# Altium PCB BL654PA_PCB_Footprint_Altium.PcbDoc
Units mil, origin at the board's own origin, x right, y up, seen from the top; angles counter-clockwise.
Board outline 866.14 x 393.7 mil, 2 copper layers (Top Layer, Bottom Layer); 1 components, 0 nets, 80 pads, 0 vias.
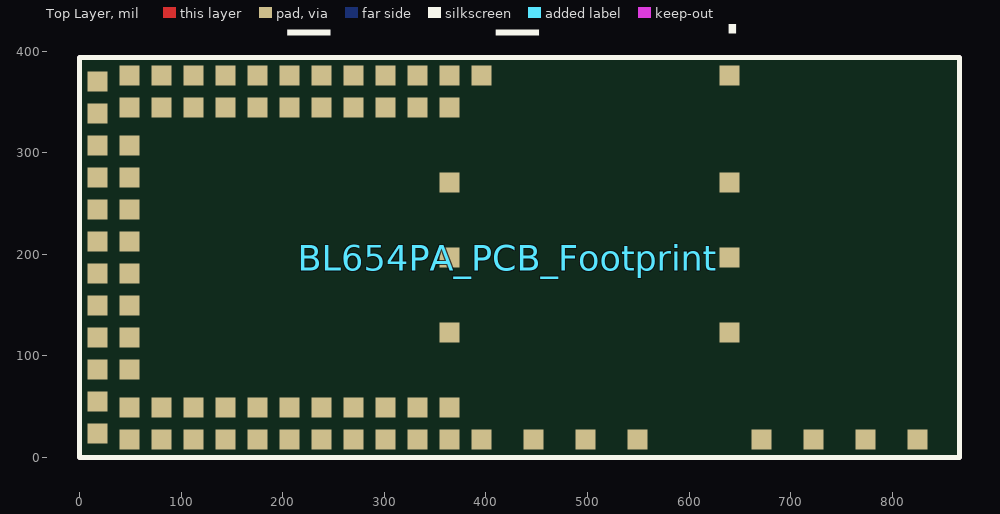
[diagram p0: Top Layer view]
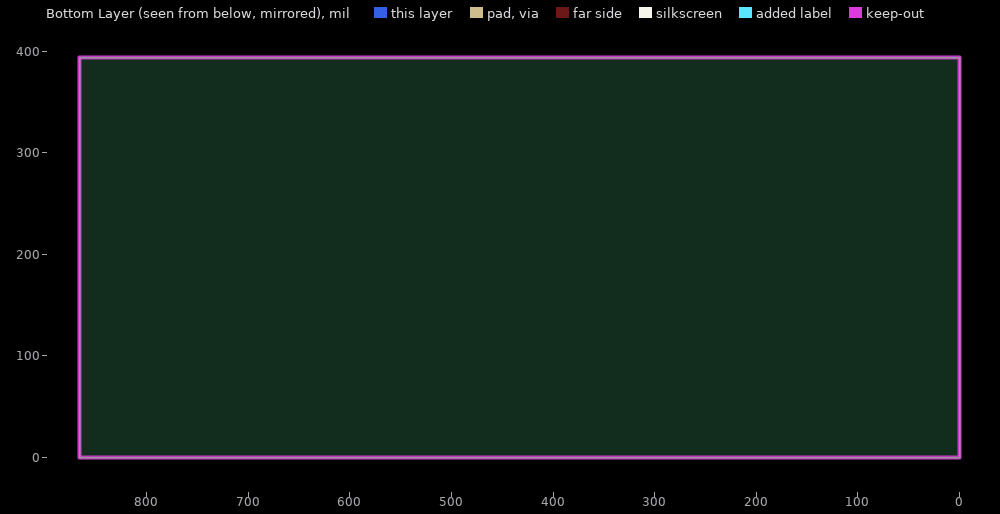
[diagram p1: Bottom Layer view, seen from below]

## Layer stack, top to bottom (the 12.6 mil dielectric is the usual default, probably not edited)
Top Solder: solder mask 0.4, Solder Resist, Dk 3.5
Top Layer: signal copper 1.4
Dielectric 1: dielectric 12.6, FR-4, Dk 4.8
Bottom Layer: signal copper 1.4
Bottom Solder: solder mask 0.4, Solder Resist, Dk 3.5

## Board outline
0,0 0,393.7 866.14,393.7 866.14,0

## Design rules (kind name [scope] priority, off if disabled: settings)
Clearance [All] p1: gap=10 ignorepadtopadclearanceinfootprint=FALSE except(0: Arc-Hole Track-Hole SMDPad-Hole THPad-Hole Via-Hole Fill-Hole Poly-Hole Region-Hole Text-Hole)
PolygonConnect [All] p1: connectstyle=Relief reliefconductorwidth=10 reliefentries=4 polygonreliefangle="90 Angle" airgapwidth=10
RoutingVias [All] p1: holewidth=28 width=50 viastyle="Through Hole" minholewidth=28 minwidth=50 maxholewidth=28 maxwidth=50
SolderMaskExpansion [All] p1: expansion=4 istentingtop=FALSE
Width [All] p1: maxlimit=10 minlimit=10 preferedwidth=10
30 further rules are at their usual default settings.

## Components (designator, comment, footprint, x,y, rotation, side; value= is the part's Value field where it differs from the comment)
BL654PA_PCB_Footprint "Comment" DVK_BL654HP 0,0 r0 top

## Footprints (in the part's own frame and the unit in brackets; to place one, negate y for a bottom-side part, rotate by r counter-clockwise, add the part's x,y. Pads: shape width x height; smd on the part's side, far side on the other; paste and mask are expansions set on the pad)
DVK_BL654HP [mm]
  rrect0% 0.5x0.5 smd mask+0.051: 0(10.05,0.45) 1(9.25,0.45) 3(8.45,0.45) 5(7.65,0.45) 7(6.85,0.45) 9(6.05,0.45) 11(5.25,0.45) 13(4.45,0.45) 15(3.65,0.45) 17(2.85,0.45) 19(2.05,0.45) 21(1.25,0.45) 23(0.45,0.6) 24(0.45,1.4) 25(0.45,2.2) 27(0.45,3) 29(0.45,3.8) 31(0.45,4.6) 33(0.45,5.4) 35(0.45,6.2) 37(0.45,7) 39(0.45,7.8) 41(0.45,8.6) 42(0.45,9.4) 43(1.25,9.55) 45(2.05,9.55) 47(2.85,9.55) 49(3.65,9.55) 51(4.45,9.55) 53(5.25,9.55) 55(6.05,9.55) 57(6.85,9.55) 59(7.65,9.55) 61(8.45,9.55) 63(9.25,9.55) 65(10.05,9.55) 66(11.35,0.45) 67(12.65,0.45) 68(13.95,0.45) 72(17.05,0.45) 73(18.35,0.45) 74(19.65,0.45) 75(20.95,0.45) 76(16.25,6.875) 77(16.25,5) 78(16.25,3.125) 79(16.25,9.55)
  rect 0.5x0.5 smd mask+0.051: 2(9.25,1.25) 4(8.45,1.25) 6(7.65,1.25) 8(6.85,1.25) 10(6.05,1.25) 12(5.25,1.25) 14(4.45,1.25) 16(3.65,1.25) 18(2.85,1.25) 20(2.05,1.25) 22(1.25,1.25) 26(1.25,2.2) 28(1.25,3) 30(1.25,3.8) 32(1.25,4.6) 34(1.25,5.4) 36(1.25,6.2) 38(1.25,7) 40(1.25,7.8) 44(1.25,8.75) 46(2.05,8.75) 48(2.85,8.75) 50(3.65,8.75) 52(4.45,8.75) 54(5.25,8.75) 56(6.05,8.75) 58(6.85,8.75) 60(7.65,8.75) 62(8.45,8.75) 64(9.25,8.75) 69(9.25,6.875) 70(9.25,5) 71(9.25,3.125)
  silkscreen extent 0,0 22,10, body extent 0.2,0.2 21.2,9.8, height 0.1

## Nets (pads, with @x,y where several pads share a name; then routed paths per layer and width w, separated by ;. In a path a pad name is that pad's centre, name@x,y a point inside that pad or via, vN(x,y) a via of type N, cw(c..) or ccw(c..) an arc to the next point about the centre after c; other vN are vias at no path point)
pads on no net: BL654PA_PCB_Footprint.0 BL654PA_PCB_Footprint.1 BL654PA_PCB_Footprint.2 BL654PA_PCB_Footprint.3 BL654PA_PCB_Footprint.4 BL654PA_PCB_Footprint.5 BL654PA_PCB_Footprint.6 BL654PA_PCB_Footprint.7 BL654PA_PCB_Footprint.8 BL654PA_PCB_Footprint.9 BL654PA_PCB_Footprint.10 BL654PA_PCB_Footprint.11 BL654PA_PCB_Footprint.12 BL654PA_PCB_Footprint.13 BL654PA_PCB_Footprint.14 BL654PA_PCB_Footprint.15 BL654PA_PCB_Footprint.16 BL654PA_PCB_Footprint.17 BL654PA_PCB_Footprint.18 BL654PA_PCB_Footprint.19 BL654PA_PCB_Footprint.20 BL654PA_PCB_Footprint.21 BL654PA_PCB_Footprint.22 BL654PA_PCB_Footprint.23 BL654PA_PCB_Footprint.24 BL654PA_PCB_Footprint.25 BL654PA_PCB_Footprint.26 BL654PA_PCB_Footprint.27 BL654PA_PCB_Footprint.28 BL654PA_PCB_Footprint.29 BL654PA_PCB_Footprint.30 BL654PA_PCB_Footprint.31 BL654PA_PCB_Footprint.32 BL654PA_PCB_Footprint.33 BL654PA_PCB_Footprint.34 BL654PA_PCB_Footprint.35 BL654PA_PCB_Footprint.36 BL654PA_PCB_Footprint.37 BL654PA_PCB_Footprint.38 BL654PA_PCB_Footprint.39 BL654PA_PCB_Footprint.40 BL654PA_PCB_Footprint.41 BL654PA_PCB_Footprint.42 BL654PA_PCB_Footprint.43 BL654PA_PCB_Footprint.44 BL654PA_PCB_Footprint.45 BL654PA_PCB_Footprint.46 BL654PA_PCB_Footprint.47 BL654PA_PCB_Footprint.48 BL654PA_PCB_Footprint.49 BL654PA_PCB_Footprint.50 BL654PA_PCB_Footprint.51 BL654PA_PCB_Footprint.52 BL654PA_PCB_Footprint.53 BL654PA_PCB_Footprint.54 BL654PA_PCB_Footprint.55 BL654PA_PCB_Footprint.56 BL654PA_PCB_Footprint.57 BL654PA_PCB_Footprint.58 BL654PA_PCB_Footprint.59 BL654PA_PCB_Footprint.60 BL654PA_PCB_Footprint.61 BL654PA_PCB_Footprint.62 BL654PA_PCB_Footprint.63 BL654PA_PCB_Footprint.64 BL654PA_PCB_Footprint.65 BL654PA_PCB_Footprint.66 BL654PA_PCB_Footprint.67 BL654PA_PCB_Footprint.68 BL654PA_PCB_Footprint.69 BL654PA_PCB_Footprint.70 BL654PA_PCB_Footprint.71 BL654PA_PCB_Footprint.72 BL654PA_PCB_Footprint.73 BL654PA_PCB_Footprint.74 BL654PA_PCB_Footprint.75 BL654PA_PCB_Footprint.76 BL654PA_PCB_Footprint.77 BL654PA_PCB_Footprint.78 BL654PA_PCB_Footprint.79

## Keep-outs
Keep-Out Layer:
  the board outline again, w4

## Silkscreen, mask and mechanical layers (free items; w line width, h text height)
Mechanical 1:
  lines w1: 669.29,0 866.14,0 866.14,393.7 669.29,393.7 669.29,0
  text "Keep Out  / Area" at 707.63,371.64 h40 r270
